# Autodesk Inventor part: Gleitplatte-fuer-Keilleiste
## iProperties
Created: 2006-05
Part Number: Gleitplatte-fuer-Keilleiste
Material: PVC-U
Document SubType Name: Modeling
Designer: Hendriks
Description: Passplatte
SBm.TeileNr: K10020023
SBm.TeileRev: 00
SBm.Rohteil: -
SBm.Werkstoff: -
SBm.WerkstNr: -
SBm.Gewicht: 0.0
SBm.BenennD: Gleitplatte - 112
SBm.BenennE: plastic liner - 112
SBm.AenIndex1: 0.0
SBm.AenDatum1: 2006-03-31
SBm.AenName1: -
SBm.AenIndex2: 0.0
SBm.AenDatum2: 2006-03-31
SBm.AenName2: -
SBm.InvVersion: 10.0
Author: Hendriks
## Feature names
1. Extrusion1
2. Bohrung3 [Hole]
3. Spiegeln1 [Mirror]
4. Bohrung4 [Hole]
5. Spiegeln2 [Mirror]
